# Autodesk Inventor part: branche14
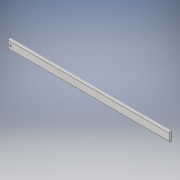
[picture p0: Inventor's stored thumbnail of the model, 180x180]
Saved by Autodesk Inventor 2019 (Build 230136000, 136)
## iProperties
Created: 2000-02
Part Number: branche14
Material: Générique
Document SubType Name: Modeling
Designer: si-nd67
Density: 1 g/cm^3
Appearance: Par défaut
Author: si-nd67
Sending System: SolidWorks 2014
Last Author: tjost
Last Saved: 2019-02-07
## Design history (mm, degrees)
feature "Congé1"
node "Solide1"
